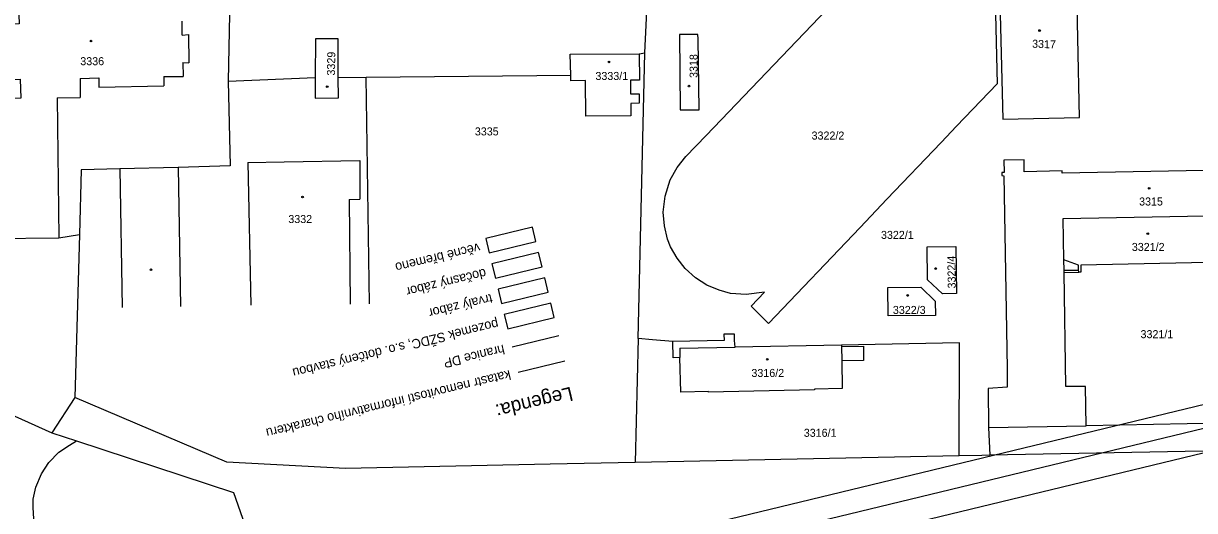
# Model space of a CAD drawing. Extents: x -738085 to -734306, y -1122197 to -1119753.
# Drawn here: x -734994.5 to -734745.8, y -1120352.8 to -1120249.4 of the extents above; entities that cross this region are included whole.
import ezdxf

# ---------------------------------------------------------------- set-up
doc = ezdxf.new("R2010")
doc.units = 0
for name, color, linetype in [('Dočasný zábor - do 1 roku', 7, 'Continuous'), ('Hranice parcel', 7, 'Continuous'), ('legenda', 7, 'Continuous'), ('Parcelní čísla', 7, 'Continuous'), ('SŽDC', 7, 'Continuous'), ('Trvalý zábor', 7, 'Continuous'), ('VBř', 7, 'Continuous'), ('Vnitřní kresba', 7, 'Continuous'), ('Vrstva 1', 7, 'Continuous'), ('Značky budov', 7, 'Continuous')]:
    doc.layers.add(name, color=color, linetype=linetype)

msp = doc.modelspace()

# ---------------------------------------------------------------- linework, layer by layer
at = {"layer": 'Dočasný zábor - do 1 roku'}
msp.add_lwpolyline([(-734894.25, -1120303.48), (-734884.34, -1120301.09), (-734885.08, -1120298.03), (-734894.99, -1120300.42)], close=True, dxfattribs=at)
at = {"layer": 'Hranice parcel'}
for p, q in [((-734862.49, -1120255.7), (-734859.9, -1120197.9)), ((-734950.5, -1120235.91), (-734950.99, -1120261.67)), ((-734863.92, -1120316.25), (-734862.49, -1120255.7)), ((-734863.69, -1120255.85), (-734862.49, -1120255.7)), ((-734950.99, -1120261.67), (-734932.53, -1120260.91)), ((-734927.62, -1120260.89), (-734921.73, -1120260.84)), ((-734921.73, -1120260.84), (-734878.26, -1120260.43)), ((-734982.61, -1120294.19), (-734983.58, -1120328.81)), ((-734863.92, -1120316.25), (-734864.54, -1120342.59)), ((-735004, -1120329.4), (-734988.44, -1120336.27)), ((-734983.58, -1120328.81), (-734988.44, -1120336.27)), ((-734789.5, -1120335.2), (-734768.77, -1120334.82)), ((-734739.68, -1120334.26), (-734768.77, -1120334.82)), ((-734988.44, -1120336.27), (-734983.2, -1120337.99)), ((-734789.5, -1120335.2), (-734789.22, -1120341.05)), ((-734705.13, -1120339.47), (-734789.22, -1120341.05)), ((-734795.77, -1120341.18), (-734864.54, -1120342.59)), ((-734864.54, -1120342.59), (-734882.62, -1120342.93))]:
    msp.add_line(p, q, dxfattribs=at)
for points in [[(-735008.98, -1120204.76), (-735000.64, -1120199.87), (-734997.94, -1120203.05), (-734997.43, -1120215.84), (-735002.6, -1120215.9), (-735001.92, -1120245.63), (-734995.53, -1120245.59), (-734995.39, -1120249.51), (-734996.74, -1120249.56), (-734996.6, -1120261.29), (-734995.16, -1120261.22), (-734995.08, -1120265.25), (-735001.61, -1120265.38), (-735001.13, -1120295.08), (-734986.97, -1120294.94), (-734982.61, -1120294.19)], [(-734770.21, -1120269.37), (-734770.92, -1120235.67), (-734787.3, -1120236.21), (-734786.45, -1120269.76), (-734770.21, -1120269.37)], [(-734851.76, -1120303.39), (-734853.96, -1120301.42), (-734855.67, -1120299.24), (-734857.04, -1120296.84), (-734857.69, -1120295.19), (-734858.36, -1120292.35), (-734858.59, -1120289.45), (-734858.21, -1120286.11), (-734857.14, -1120282.64), (-734855.68, -1120280.02), (-734853.78, -1120277.67), (-734849.51, -1120273.21), (-734819.03, -1120241.37)], [(-734788.04, -1120247.45), (-734787.7, -1120262.25), (-734796.32, -1120271.24), (-734799.58, -1120274.67), (-734811.15, -1120286.74), (-734816.81, -1120292.74), (-734836.25, -1120313.12), (-734839.95, -1120309.41), (-734837.12, -1120306.44), (-734841, -1120306.94), (-734844.29, -1120306.7), (-734846.76, -1120306.03), (-734849.35, -1120304.94), (-734851.76, -1120303.39)], [(-734927.62, -1120260.89), (-734927.64, -1120252.69), (-734932.49, -1120252.72), (-734932.53, -1120260.91)], [(-734851.22, -1120252.67), (-734851.23, -1120251.76), (-734855.18, -1120251.77), (-734855, -1120267.78), (-734851, -1120267.75), (-734851.22, -1120252.67)], [(-734878.26, -1120260.43), (-734878.36, -1120255.96), (-734863.69, -1120255.85)], [(-734863.69, -1120255.85), (-734863.65, -1120261.45), (-734865.56, -1120261.47), (-734865.53, -1120264.37), (-734863.72, -1120264.35), (-734863.71, -1120266.37), (-734865.52, -1120266.39), (-734865.49, -1120269.03), (-734875.08, -1120269.1), (-734875.15, -1120261.55), (-734878.23, -1120261.58), (-734878.26, -1120260.43)], [(-734950.99, -1120261.67), (-734950.58, -1120279.65), (-734961.64, -1120280.02), (-734974.05, -1120280.31), (-734982.22, -1120280.5), (-734982.61, -1120294.19)], [(-734932.53, -1120260.91), (-734932.55, -1120265.25), (-734927.61, -1120265.24), (-734927.62, -1120260.89)], [(-734921.01, -1120308.95), (-734921.73, -1120260.84)], [(-734723.98, -1120279.74), (-734732.02, -1120279.99), (-734732.09, -1120277.29), (-734736.31, -1120277.46), (-734736.24, -1120280.12), (-734736.23, -1120280.47), (-734773.85, -1120281.17), (-734773.86, -1120280.72), (-734781.95, -1120280.95), (-734781.94, -1120278.36), (-734786.28, -1120278.43), (-734786.18, -1120281.07), (-734786.71, -1120281.08), (-734786.69, -1120281.71), (-734786.25, -1120281.73), (-734785.59, -1120322.68), (-734785.53, -1120326.63), (-734789.62, -1120326.88), (-734789.5, -1120335.2)], [(-734773.51, -1120299.59), (-734773.65, -1120290.8), (-734739.68, -1120290.17)], [(-734739.68, -1120290.17), (-734738.58, -1120291.79), (-734737.61, -1120294.26), (-734737.56, -1120295.63), (-734739.16, -1120299.99), (-734739.14, -1120301.09), (-734739.14, -1120301.57), (-734739.63, -1120301.58), (-734739.65, -1120300.07), (-734769.92, -1120300.74), (-734769.89, -1120302.23), (-734770.37, -1120302.24), (-734770.38, -1120301.76), (-734770.4, -1120300.75), (-734773.51, -1120299.59)], [(-734796.29, -1120306.76), (-734799.31, -1120306.79), (-734802.45, -1120303.81), (-734802.54, -1120296.82), (-734796.46, -1120296.75), (-734796.29, -1120306.76)], [(-734768.77, -1120334.82), (-734768.94, -1120326.46), (-734773.09, -1120326.46), (-734773.47, -1120302.28), (-734773.48, -1120301.8), (-734773.51, -1120299.59)], [(-734800.81, -1120311.39), (-734810.85, -1120311.48), (-734810.91, -1120305.43), (-734803.9, -1120305.37), (-734800.86, -1120308.36), (-734800.81, -1120311.39)], [(-734856.58, -1120316.93), (-734860.88, -1120316.53), (-734863.92, -1120316.25)], [(-734820.75, -1120317.72), (-734843.34, -1120318.11), (-734843.44, -1120316.67), (-734843.47, -1120315.33), (-734845.73, -1120315.37), (-734845.7, -1120316.71), (-734856.58, -1120316.93)], [(-734820.75, -1120317.72), (-734820.75, -1120318), (-734816.06, -1120317.92), (-734816.05, -1120320.95), (-734820.69, -1120321.04), (-734820.59, -1120326.88), (-734826.5, -1120327.02), (-734826.5, -1120327.16), (-734849, -1120327.7), (-734849, -1120327.56), (-734854.89, -1120327.7), (-734855.05, -1120320.3), (-734856.48, -1120320.37), (-734856.58, -1120316.93)], [(-734795.77, -1120341.18), (-734795.65, -1120317.2), (-734820.75, -1120317.72)], [(-734882.62, -1120342.93), (-734926.09, -1120343.86), (-734951.28, -1120342.51), (-734983.58, -1120328.81)], [(-734987.62, -1120364.99), (-734990.19, -1120361.1), (-734991.31, -1120357.96), (-734991.92, -1120356.42), (-734992.3, -1120354.58), (-734992.44, -1120352.17), (-734992.41, -1120350.36), (-734991.84, -1120347.81), (-734990.65, -1120344.99), (-734989.08, -1120342.62), (-734987.01, -1120340.42), (-734984.73, -1120338.93), (-734983.2, -1120337.99)], [(-734983.2, -1120337.99), (-734949.91, -1120348.95), (-734941, -1120374.24)], [(-734789.22, -1120341.05), (-734790.95, -1120341.08), (-734795.77, -1120341.18)]]:
    msp.add_lwpolyline(points, dxfattribs=at)
at = {"layer": 'legenda'}
for p, q in [((-734880.81, -1120315.71), (-734890.72, -1120318.11)), ((-734879.51, -1120321.1), (-734889.42, -1120323.49))]:
    msp.add_line(p, q, dxfattribs=at)
at = {"layer": 'SŽDC'}
msp.add_lwpolyline([(-734891.65, -1120314.25), (-734881.74, -1120311.86), (-734882.48, -1120308.8), (-734892.39, -1120311.19)], close=True, dxfattribs=at)
at = {"layer": 'Trvalý zábor'}
msp.add_lwpolyline([(-734892.95, -1120308.87), (-734883.04, -1120306.47), (-734883.78, -1120303.41), (-734893.69, -1120305.81)], close=True, dxfattribs=at)
at = {"layer": 'VBř'}
for p, q in [((-734886.38, -1120292.64), (-734896.29, -1120295.04)), ((-734886.38, -1120292.64), (-734896.29, -1120295.04)), ((-734885.64, -1120295.7), (-734886.38, -1120292.64)), ((-734885.64, -1120295.7), (-734886.38, -1120292.64)), ((-734896.29, -1120295.04), (-734895.55, -1120298.1)), ((-734896.29, -1120295.04), (-734895.55, -1120298.1)), ((-734895.55, -1120298.1), (-734885.64, -1120295.7)), ((-734895.55, -1120298.1), (-734885.64, -1120295.7))]:
    msp.add_line(p, q, dxfattribs=at)
at = {"layer": 'Vnitřní kresba'}
for p, q in [((-734960.81, -1120251.9), (-734960.8, -1120248.97)), ((-734960.81, -1120251.9), (-734959.42, -1120251.76)), ((-734959.42, -1120251.76), (-734959.36, -1120257.77)), ((-734960.63, -1120257.71), (-734959.36, -1120257.77)), ((-734960.63, -1120257.71), (-734960.6, -1120260.67)), ((-734982.48, -1120261.11), (-734978.5, -1120260.97)), ((-734982.48, -1120261.11), (-734982.42, -1120265.14)), ((-734978.5, -1120260.97), (-734978.46, -1120262.94)), ((-734978.46, -1120262.94), (-734964.65, -1120262.66)), ((-734964.69, -1120260.71), (-734960.6, -1120260.67)), ((-734964.69, -1120260.71), (-734964.65, -1120262.66)), ((-734987.34, -1120265.21), (-734982.42, -1120265.14)), ((-734987.34, -1120265.21), (-734986.97, -1120294.94)), ((-734974.05, -1120280.31), (-734973.53, -1120309.69)), ((-734961.64, -1120280.02), (-734961.15, -1120309.47)), ((-734946.85, -1120278.94), (-734939.13, -1120278.81)), ((-734946.85, -1120278.94), (-734946.2, -1120309.22)), ((-734939.13, -1120278.81), (-734923.07, -1120278.5)), ((-734923.07, -1120278.5), (-734923.04, -1120286.75)), ((-734925.29, -1120286.77), (-734923.04, -1120286.75)), ((-734925.29, -1120286.77), (-734925.07, -1120309.01)), ((-734773.48, -1120301.8), (-734770.38, -1120301.76)), ((-734773.47, -1120302.28), (-734770.37, -1120302.24)), ((-734855.09, -1120318.31), (-734843.34, -1120318.11)), ((-734855.09, -1120318.31), (-734855.05, -1120320.3)), ((-734820.75, -1120318), (-734820.69, -1120321.04))]:
    msp.add_line(p, q, dxfattribs=at)
at = {"layer": 'Vrstva 1'}
for points in [[(-734534.27, -1119984.39), (-735554.91, -1120230.88), (-735485.2, -1120519.57), (-734464.55, -1120273.08)], [(-734470.58, -1120269.4), (-735481.51, -1120513.53), (-735548.88, -1120234.56), (-734537.95, -1119990.43)], [(-734541.63, -1119996.45), (-735348.44, -1120191.3), (-735283.42, -1120460.56), (-734476.61, -1120265.71)]]:
    msp.add_lwpolyline(points, close=True, dxfattribs=at)
at = {"layer": 'Značky budov'}
for centre in [(-734778.68, -1120250.94), (-734980.13, -1120253.16), (-734870.14, -1120257.6), (-734929.98, -1120262.85), (-734853.15, -1120262.73), (-734755.4, -1120284.41), (-734935.22, -1120286.26), (-734755.7, -1120294.05), (-734967.42, -1120301.7), (-734800.73, -1120301.43), (-734806.69, -1120307.14), (-734836.51, -1120320.69)]:
    msp.add_circle(centre, 0.175, dxfattribs=at)

# ---------------------------------------------------------------- texts
at = {"layer": 'legenda'}
for s, height, p in [('věcné břemeno', 2, (-734897.77, -1120296.01)), ('dočasný zábor', 2, (-734896.47, -1120301.4)), ('trvalý zábor', 2, (-734895.17, -1120306.78)), ('pozemek SŽDC, s.o. dotčený stavbou', 2, (-734893.87, -1120312.17)), ('hranice DP', 2, (-734892.57, -1120317.55)), ('katastr nemovitostí informativního charakteru', 2, (-734891.27, -1120322.94)), ('Legenda:', 3, (-734878.21, -1120326.48))]:
    msp.add_text(s, height=height, rotation=193.5769, dxfattribs=at).set_placement(p)
at = {"layer": 'Parcelní čísla'}
for s, rotation, p in [('3317', 358, (-734780.29, -1120254.57)), ('3329', 89, (-734928.34, -1120260.5)), ('3318', 90, (-734851.31, -1120261)), ('3322/4', 91, (-734796.47, -1120305.65))]:
    msp.add_text(s, height=1.7, rotation=rotation, dxfattribs=at).set_placement(p)
for s, p in [('3336', (-734982.42, -1120258.29)), ('3333/1', (-734873.01, -1120261.42)), ('3335', (-734898.62, -1120273.19)), ('3322/2', (-734827.1, -1120274.07)), ('3315', (-734757.54, -1120288.06)), ('3332', (-734938.24, -1120291.78)), ('3322/1', (-734812.36, -1120295.15)), ('3321/2', (-734759.08, -1120297.7)), ('3322/3', (-734809.83, -1120311.07)), ('3321/1', (-734757.23, -1120316.21)), ('3316/2', (-734839.88, -1120324.44)), ('3316/1', (-734828.76, -1120337.14))]:
    msp.add_text(s, height=1.7, dxfattribs=at).set_placement(p)

doc.saveas('drawing.dxf')
